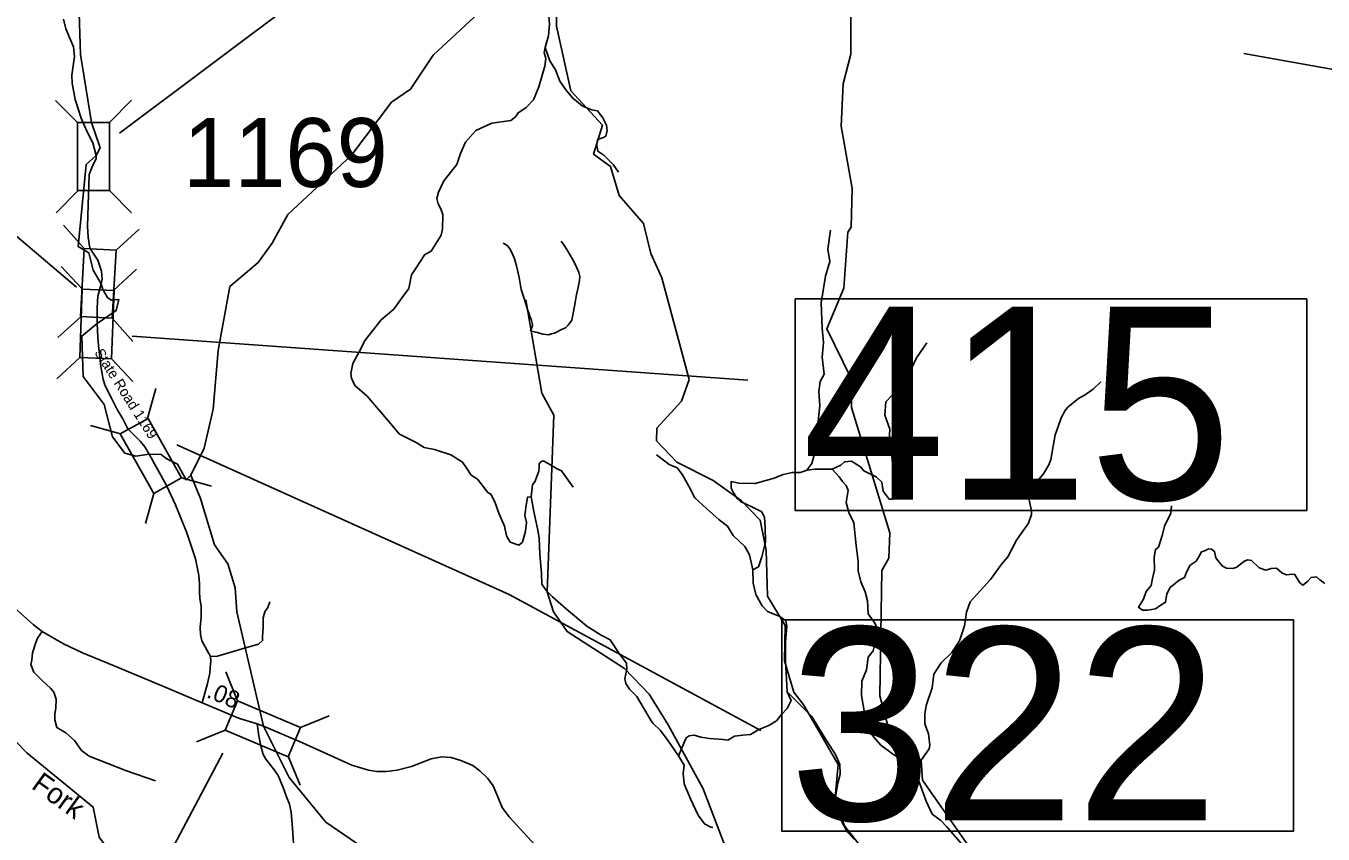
# Model space of a CAD drawing. Extents: x 1248224 to 1454986, y 825081 to 985870.
# Drawn here: x 1290579 to 1300002, y 874876 to 880743 of the extents above; entities that cross this region are included whole.
import ezdxf

# ---------------------------------------------------------------- set-up
doc = ezdxf.new("R2010")
doc.units = 0
for name, color, linetype in [('Exist Hydrographic Creek Single Shore', 7, 'Continuous'), ('Exist Hydrographic Creek Single Shore Label', 7, 'Continuous'), ('Exist Hydrographic Misc Water Feature', 7, 'Continuous'), ('Exist Road Non-System Type 51', 7, 'Continuous'), ('Exist Road Secondary Mileage Hundredths English Label', 7, 'Continuous'), ('Exist Road Secondary Structure Standard Bridge CELL', 7, 'Continuous'), ('Exist Road Secondary Structure Standard Bridge Number Label', 7, 'Continuous'), ('Exist Road Secondary Type 41 Attributed', 7, 'Continuous'), ('Exist Road Secondary Type 51 Attributed', 7, 'Continuous'), ('Exist Road Secondary Type 51 Label', 7, 'Continuous'), ('Exist Road Secondary Type 51 Number Label', 7, 'Continuous')]:
    doc.layers.add(name, color=color, linetype=linetype)

msp = doc.modelspace()

# ---------------------------------------------------------------- linework, layer by layer
at = {"layer": 'Exist Hydrographic Creek Single Shore'}
for points in [[(1291089.2, 879801.8), (1291118.8, 879857.6), (1291055.8, 880042.6), (1290976.7, 880536.6), (1290966.8, 880835.6)], [(1300225, 880400.4), (1299426.9, 880544.5)], [(1291126.6, 878871.1), (1291067.1, 878969.7), (1291036.4, 879096.4), (1290958.8, 879141.8), (1291016.8, 879737.6), (1291089.2, 879801.8)], [(1291097.8, 878582.1), (1291235.2, 878676.7), (1291253, 878756.9), (1291198.6, 878752.9), (1291172.9, 878771.7), (1291136.8, 878830.4), (1291126.6, 878871.1)], [(1291474.7, 877633.8), (1291378.7, 877620.9), (1291297.9, 877641.4), (1291208.9, 877761.3), (1291147.9, 877995.7), (1290993.9, 878199), (1290984.8, 878491.3), (1291097.8, 878582.1)], [(1291776.9, 877480.8), (1291742.8, 877447.7), (1291681.4, 877560.6), (1291596.8, 877602.5), (1291561.7, 877631.8), (1291474.7, 877633.8)], [(1292305.9, 875658.3), (1292111.9, 876489.2), (1292098.9, 876663.5), (1292044.9, 876838.5), (1291947.9, 876975.1), (1291847.9, 877311.9), (1291776.9, 877480.8)], [(1292627.6, 873988.5), (1292479.6, 873915.9), (1292338.8, 873797.9), (1292148.7, 873938.9), (1291945.6, 874109.4), (1291863.9, 874235.6), (1291719.1, 874279.3), (1291608.9, 874358.9), (1291493.9, 874426.9), (1291323.9, 874630.5), (1291192.9, 874741.4), (1291111.9, 874854.7), (1291067.9, 875072.3), (1290584.9, 875466.1), (1290015.9, 876048.6), (1289907.9, 876073.7)], [(1293365, 874546.9), (1292757.9, 874962.9), (1292491, 875286.7), (1292305.9, 875658.3)]]:
    msp.add_lwpolyline(points, dxfattribs=at)
at = {"layer": 'Exist Hydrographic Misc Water Feature'}
for points in [[(1298185, 873895.5), (1298130.1, 874031.1), (1297898.1, 874101.5), (1297446, 874681.8), (1297415.1, 874807), (1297093, 875266.6), (1297082.8, 875412), (1296844, 875655.6), (1296783, 875880.1), (1296796.9, 876789.2), (1296849, 876880), (1296854, 877063.8), (1296576, 877972.1), (1296572.9, 878188.9), (1296397.9, 878543.6), (1296522, 878839.9), (1296548.9, 879246.4), (1296575, 879282), (1296581.9, 879564.1), (1296501, 880015.6), (1296516.9, 880323.9), (1296571.9, 880539.4), (1296575.9, 881724.4)], [(1296712.1, 874699.7), (1296526, 874936.5), (1296456, 875115.2), (1296479, 875380.7), (1296231, 875812.4), (1296158, 875905.8), (1296089, 876133.6), (1296095, 876389.6), (1295967, 876602.3), (1295958, 876937.3), (1295914, 877154.9), (1295775, 877298.8), (1295570.9, 877444.1), (1295306.9, 877577.4), (1295160.9, 877731.3), (1295162.9, 877823.2), (1295342.9, 878019.8), (1295397, 878176.4), (1295198, 878915.7), (1295118.9, 879091.2), (1295065.9, 879309), (1294887.9, 879512.8), (1294825.9, 879724.1), (1294702.9, 879812), (1294766.8, 880024.1), (1294538.9, 880271.6), (1294433.8, 880743.1), (1294435.9, 881160)], [(1291776.9, 877480.8), (1291873.9, 877679), (1291938.9, 877960.1), (1291974.8, 878386.1), (1292060.9, 878850.6), (1292265.8, 879027), (1292368.8, 879166), (1292482.9, 879373.9), (1292943.8, 879804.6), (1293235.8, 880189.3), (1293371.9, 880285.1), (1293536.8, 880531.3), (1293869.8, 880839.8)], [(1294774, 873878.5), (1294918.1, 873957.7), (1295020, 874057.5), (1295178, 874346.4), (1295603, 874685.9), (1295663, 874773.3), (1295499, 875203.3), (1295244, 875668.1), (1295107, 875890.7), (1294928, 876078.2), (1294510, 876346), (1294412.9, 876489.1), (1294367, 876634.4), (1294415, 877917), (1294326.9, 878076.3), (1294209.9, 878754.9)], [(1298387.1, 878159.8), (1298331.8, 878105.1), (1298274.8, 878064.4), (1298226.1, 878037.5), (1298148.4, 877975.9), (1298127.8, 877951.6), (1298102.6, 877902.9), (1298057.5, 877775.8), (1298025.1, 877595.8), (1298010, 877556.8), (1297972.5, 877491.1), (1297927.2, 877440.3), (1297877.1, 877357.6), (1297867.7, 877301.9), (1297883.8, 877221.2), (1297883.2, 877197.4), (1297861.6, 877132.2), (1297776.6, 877010), (1297713.5, 876889.8), (1297668.2, 876838.2), (1297587.4, 876724.1), (1297439.3, 876562.1), (1297411.4, 876486.3), (1297397, 876388.9), (1297362.3, 876278), (1297306.2, 876194.6), (1297228.2, 876119.1), (1297174.2, 876036.4), (1297161.7, 875936.6), (1297118.6, 875809.3), (1297109, 875747.2), (1297109.2, 875675.7), (1297135.5, 875603.1), (1297145.5, 875522.4), (1297140.9, 875494.6), (1297082.8, 875412)]]:
    msp.add_lwpolyline(points, dxfattribs=at)
at = {"layer": 'Exist Road Non-System Type 51'}
for points in [[(1294349.1, 880939.6), (1294376, 880846.2), (1294381.9, 880754.6), (1294376, 880671.9), (1294352.4, 880586.2)], [(1294352.4, 880586.2), (1294343.5, 880550.8), (1294355.3, 880506.4), (1294349.4, 880450.3), (1294305.1, 880302.6), (1294266.8, 880208), (1294210.7, 880148.9), (1294154.6, 880113.5), (1294136.8, 880083.9), (1294101.4, 880057.3), (1293962.7, 880036.7), (1293847.5, 879983.5), (1293773.7, 879900.8), (1293735.3, 879818), (1293709.1, 879737.8), (1293614.7, 879619.7), (1293576.3, 879536.9), (1293564.5, 879489.7), (1293573.3, 879451.2), (1293594, 879415.8), (1293608.7, 879374.4), (1293605.8, 879268.1), (1293596.9, 879223.7), (1293523.1, 879108.5), (1293475.9, 879084.9), (1293413.9, 878987.4), (1293381.4, 878937.2), (1293360.7, 878836.7), (1293313.5, 878771.7), (1293251.5, 878686), (1293160, 878609.2), (1293044.8, 878461.5), (1293003.5, 878381.7), (1292953.8, 878291.6), (1292939, 878220.7), (1292944.9, 878185.2), (1292968.6, 878132), (1293057.1, 878055.2), (1293157.5, 877940), (1293228.4, 877857.2), (1293293.3, 877780.4), (1293414.4, 877718.4), (1293473.4, 877682.9), (1293547.2, 877668.2), (1293665.3, 877629.7), (1293751, 877576.6), (1293777.5, 877538.2), (1293813, 877482), (1293860.2, 877452.5), (1293935.6, 877356.7), (1293956.3, 877344.9), (1293985.8, 877288.7), (1294015.3, 877206), (1294056.6, 877111.4), (1294071.4, 877040.5), (1294098, 876996.2), (1294160, 876972.6), (1294186.5, 876996.2), (1294207.2, 877076), (1294216.1, 877138), (1294204.3, 877188.3), (1294210.2, 877247.4), (1294222, 877321.2), (1294248.5, 877324.2)], [(1294352.4, 880586.2), (1294385.1, 880490.7), (1294426.3, 880424.4), (1294458.3, 880342), (1294501.8, 880280.2), (1294552.1, 880218.4), (1294620.7, 880163.5), (1294687, 880133.7), (1294730.5, 880126.8), (1294769.3, 880076.5), (1294796.8, 880023.9), (1294801.3, 879985), (1294792.2, 879943.8), (1294773.9, 879934.6), (1294730.5, 879918.6), (1294725.9, 879879.7), (1294735, 879833.9), (1294778.5, 879806.4), (1294844.8, 879737.8), (1294883.7, 879682.9)], [(1296251.1, 877517.4), (1296288.1, 877567), (1296315.5, 877663.1), (1296322.4, 877731.8), (1296336.1, 877896.6), (1296346.4, 877985.8), (1296339.5, 878088.8), (1296349.8, 878160.9), (1296377.3, 878215.8), (1296363.5, 878339.4), (1296373.8, 878445.8), (1296363.5, 878548.8), (1296356.7, 878734.2), (1296387.5, 878926.4), (1296418.2, 879033.5), (1296404.5, 879122.8), (1296425.1, 879260.1)], [(1294245.4, 878526.4), (1294260.2, 878568.1), (1294260.4, 878576.1), (1294250.9, 878604.3), (1294237.7, 878644.6), (1294222.5, 878684.9), (1294203.8, 878749.3), (1294177.4, 878829.9), (1294163.1, 878918.2), (1294142.8, 879002.7), (1294127.8, 879053), (1294110.6, 879093.4), (1294095.3, 879125.7), (1294081.6, 879142), (1294067.8, 879154.3), (1294046, 879166.7)], [(1294245.4, 878526.4), (1294263.3, 878524), (1294283.2, 878519.6), (1294295.2, 878517.4), (1294335, 878506.5), (1294356.9, 878502.1), (1294378.9, 878501.7), (1294395.1, 878507.3), (1294419.2, 878512.9), (1294475.8, 878541.7), (1294500, 878551.3), (1294518.4, 878570.9), (1294545.2, 878608.4), (1294556.4, 878670.2), (1294569.7, 878736), (1294578.9, 878793.8), (1294589.9, 878843.6), (1294596.5, 878871.5), (1294601, 878895.5), (1294603.6, 878925.4), (1294596.1, 878953.6), (1294575.1, 879004), (1294550, 879050.6), (1294517.1, 879107.3), (1294495.8, 879139.7), (1294466.6, 879180.3)], [(1295860, 876794.5), (1295901.2, 876817.1), (1295925.2, 876889.2), (1295952.7, 876995.6), (1295949.3, 877098.6), (1295945.8, 877174.1), (1295925.2, 877215.3), (1295856.6, 877249.6), (1295770.9, 877290.8), (1295746.9, 877311.4), (1295719.4, 877352.6), (1295702.3, 877387), (1295702.3, 877435), (1295757.2, 877424.7), (1295877.2, 877421.3), (1296014.4, 877459), (1296079.6, 877486.5), (1296144.8, 877500.2), (1296206.5, 877500.2), (1296251.1, 877517.4), (1296309.4, 877524.3), (1296384.9, 877524.3), (1296436.4, 877524.3), (1296498.1, 877555.2), (1296525.6, 877579.2), (1296577, 877582.6), (1296642.2, 877541.4), (1296666.2, 877514), (1296755.4, 877469.3), (1296796.6, 877431.6), (1296806.9, 877366.4), (1296851.4, 877308), (1296874.6, 877306.6), (1296881.5, 877323.8), (1296898.6, 877354.7), (1296888.4, 877389), (1296874.6, 877461.1), (1296874.6, 877567.5), (1296867.8, 877643), (1296847.2, 877694.5), (1296854.1, 877814.7), (1296819.8, 877917.7), (1296826.6, 878013.8), (1296871.2, 878061.9), (1296943.2, 878103.1), (1296991.3, 878209.5), (1297049.6, 878333.1), (1297125.1, 878442.9)], [(1295860, 876794.5), (1295836.1, 876902.9), (1295801.8, 876964.7), (1295716, 877043.7), (1295674.8, 877112.3), (1295616.5, 877157), (1295523.9, 877239.3), (1295438.1, 877318.3), (1295397, 877397.3), (1295348.9, 877483.1), (1295311.2, 877534.6), (1295252.9, 877558.6), (1295198, 877599.8), (1295160.3, 877630.7)], [(1294248.5, 877324.2), (1294257.4, 877389.2), (1294260.4, 877412.8), (1294278.1, 877439.4), (1294289.9, 877471.9), (1294304.6, 877510.3), (1294307.6, 877539.9), (1294307.6, 877563.5), (1294319.4, 877578.3), (1294337.1, 877587.1), (1294372.5, 877566.4), (1294434.5, 877531), (1294470, 877513.3), (1294555.6, 877395.1)], [(1296436.4, 877524.3), (1296487.6, 877469.5), (1296511.6, 877435.2), (1296539, 877407.7), (1296552.8, 877369.9), (1296539, 877284.1), (1296556.2, 877212), (1296593.9, 877136.5), (1296611.1, 876971.7), (1296624.8, 876855), (1296624.8, 876786.3), (1296645.4, 876707.4), (1296676.3, 876635.3), (1296693.4, 876570.1), (1296696.8, 876474), (1296741.4, 876415.6), (1296762, 876374.4), (1296751.7, 876274.9), (1296734.6, 876206.2), (1296696.8, 876161.6), (1296686.6, 876068.9), (1296652.1, 875986.1), (1296648.7, 875883.1), (1296672.7, 875742.3), (1296689.8, 875642.8), (1296741.3, 875577.5), (1296789.3, 875522.6), (1296875.1, 875457.4), (1296943.7, 875416.2), (1297012.3, 875371.6), (1297043.2, 875320.1), (1297118.6, 875114.1), (1297163.2, 875021.4), (1297225, 874973.4), (1297269.6, 874928.7), (1297379.3, 874801.7)], [(1294248.5, 877324.2), (1294269.2, 877218.8), (1294298.7, 877082.9), (1294307.6, 877026.8), (1294313.5, 876905.6), (1294325.3, 876769.7), (1294328.2, 876690), (1294357.7, 876645.6), (1294405, 876598.4), (1294505.4, 876509.7), (1294653, 876385.6), (1294759.3, 876320.6), (1294824.2, 876285.2), (1294889.2, 876187.7), (1294942.3, 876116.8), (1294945.3, 876072.5), (1294930.5, 876004.5), (1294936.4, 875969.1), (1294963, 875927.7), (1295016.1, 875874.5), (1295121.5, 875699), (1295136.3, 875678.3), (1295186.4, 875631.1), (1295239.6, 875560.2), (1295319.3, 875444.9)], [(1300015.1, 876695.4), (1299978.7, 876722.1), (1299954.4, 876744), (1299915.5, 876739.1), (1299888.9, 876710), (1299854.9, 876683.3), (1299833, 876700.3), (1299794.2, 876763.4), (1299755.4, 876761), (1299733.5, 876758.6), (1299702, 876773.1), (1299663.1, 876807.1), (1299626.7, 876804.7), (1299587.9, 876792.6), (1299539.4, 876809.6), (1299483.5, 876863), (1299454.4, 876867.8), (1299427.7, 876855.7), (1299376.8, 876814.4), (1299347.6, 876804.7), (1299301.5, 876807.1), (1299272.4, 876821.7), (1299248.1, 876850.8), (1299223.8, 876882.4), (1299213.1, 876928), (1299191.3, 876945), (1299169.5, 876947.4), (1299147.6, 876935.2), (1299118.5, 876925.5), (1299099.1, 876889.1), (1299079.7, 876857.5), (1299036, 876828.4), (1299009.3, 876777.4), (1298997.1, 876738.5), (1298958.3, 876719.1), (1298931.6, 876697.2), (1298892.8, 876665.7), (1298868.5, 876619.5), (1298858.8, 876558.8), (1298827.3, 876539.4), (1298786, 876510.2), (1298727.7, 876502.9), (1298691.3, 876500.5), (1298662.2, 876522.4), (1298698.6, 876580.6), (1298718, 876636.5), (1298754.4, 876680.2), (1298764.1, 876731.2), (1298778.7, 876794.4), (1298776.3, 876886.7), (1298786, 876942.5), (1298807.8, 876959.5), (1298837, 877051.8), (1298851.5, 877112.6), (1298897.6, 877204.8), (1298902.5, 877258.3)], [(1295319.3, 875444.9), (1295376.4, 875575.8), (1295396.9, 875589.5), (1295434.7, 875593), (1295482.7, 875579.2), (1295544.4, 875569), (1295643.9, 875562.1), (1295678.2, 875558.7), (1295726.3, 875586.1), (1295788, 875593), (1295842.9, 875599.8), (1295904.6, 875634.2), (1295976.7, 875665.1), (1296031.6, 875699.4), (1296069.3, 875744), (1296110.5, 875788.7), (1296137.9, 875847), (1296110.5, 875908.8), (1296096.7, 876135.4), (1296096.7, 876265.8), (1296107, 876386), (1296100.2, 876423.7), (1296055.6, 876454.6), (1295966.4, 876492.4), (1295928.6, 876533.6), (1295880.6, 876616), (1295863.5, 876698.4), (1295860, 876794.5)], [(1291919.8, 876166.5), (1291970.2, 876168.4), (1292150.3, 876221.6), (1292241.8, 876248.1), (1292268.4, 876254.1), (1292297.9, 876280.6), (1292297.9, 876310.2), (1292303.8, 876375.2), (1292303.8, 876446.1), (1292315.6, 876490.4), (1292336.3, 876520), (1292351.1, 876561.3)], [(1290697.3, 876347.1), (1290663.1, 876299.1), (1290651.3, 876266.6), (1290627.7, 876192.7), (1290621.8, 876139.5), (1290615.9, 876107), (1290636.5, 876050.9), (1290698.5, 875988.9), (1290757.6, 875935.7), (1290781.2, 875906.1), (1290798.9, 875855.9), (1290796, 875790.9), (1290790, 875749.5), (1290790, 875705.2), (1290804.8, 875649.1), (1290869.8, 875610.7), (1290931.8, 875554.5), (1290982, 875483.6), (1291038.1, 875442.3), (1291309.7, 875335.9), (1291519.3, 875262)], [(1296596.5, 874838), (1296545, 874892.9), (1296501, 874973.6), (1296466.7, 875062.9), (1296459.9, 875145.2), (1296477, 875244.8), (1296494.2, 875310), (1296490.8, 875382.1), (1296459.9, 875454.2), (1296377.6, 875581.2), (1296288.4, 875728.8), (1296110.5, 875908.8), (1296137.9, 875847)], [(1295319.3, 875444.9), (1295360.6, 875377), (1295354.7, 875314.9), (1295360.6, 875241.1), (1295407.9, 875131.8), (1295464, 875013.6), (1295508.1, 874950.1), (1295555.3, 874926.5), (1295570.1, 874923.5)]]:
    msp.add_lwpolyline(points, dxfattribs=at)
at = {"layer": 'Exist Road Secondary Structure Standard Bridge CELL'}
for p, q in [((1290794.7, 880203.3), (1290954.8, 880043.3)), ((1291346.4, 880203.5), (1291186.4, 880043.4)), ((1290959.1, 879547.6), (1290799.1, 879387.5)), ((1291185.4, 879547.6), (1291345.6, 879387.6)), ((1290851.9, 879297.2), (1291002.9, 879128.6)), ((1291402.7, 879266.8), (1291234.1, 879115.8)), ((1290989.9, 878831.5), (1290836, 878997.5)), ((1291216.1, 878822.9), (1291382.1, 878976.7)), ((1290979.7, 878633.3), (1290811.1, 878482.3)), ((1291205.8, 878620.9), (1291356.8, 878452.2)), ((1290803.9, 878182.3), (1290969.9, 878336.1)), ((1291355.2, 878161.3), (1291201.3, 878327.3)), ((1291462.7, 877892.5), (1291523.5, 878110.5)), ((1291265.5, 877781.3), (1291047.5, 877842.1)), ((1291927.8, 877401.9), (1291709.8, 877462.7)), ((1291447.3, 877130.9), (1291508.1, 877349)), ((1292032, 876053.2), (1292117.1, 875843.5)), ((1292573.4, 875649.6), (1292783.1, 875734.8)), ((1291817.3, 875545), (1292027, 875630.1)), ((1292485.4, 875441.1), (1292570.5, 875231.4))]:
    msp.add_line(p, q, dxfattribs=at)
for points in [[(1291186.4, 880043.4), (1291186.5, 879547.6), (1290954.9, 879547.6), (1290954.8, 880043.3)], [(1291234.1, 879115.8), (1291206.8, 878620.8), (1290975.6, 878633.5), (1291002.9, 879128.6)], [(1290969.9, 878336.1), (1290988.8, 878831.5), (1291220.2, 878822.7), (1291201.3, 878327.3)], [(1291508.1, 877349), (1291264.6, 877780.8), (1291466.3, 877894.5), (1291709.8, 877462.7)], [(1292117.1, 875843.5), (1292573.8, 875650.6), (1292483.7, 875437.3), (1292027, 875630.1)]]:
    msp.add_lwpolyline(points, close=True, dxfattribs=at)
at = {"layer": 'Exist Road Secondary Structure Standard Bridge Number Label'}
for p, q in [((1290947.6, 878846.4), (1286961.2, 882216.8)), ((1291258.3, 879964.7), (1292953.7, 881236.2)), ((1291352, 878490.4), (1295824.7, 878170.9)), ((1292008.9, 875464.1), (1289936.5, 871537.4))]:
    msp.add_line(p, q, dxfattribs=at)
for points in [[(1296167.6, 878761.7), (1299883.5, 878761.7), (1299883.5, 877225.2), (1296167.6, 877225.2)], [(1296070.8, 876432.7), (1299786.7, 876432.7), (1299786.7, 874896.3), (1296070.8, 874896.3)]]:
    msp.add_lwpolyline(points, close=True, dxfattribs=at)
msp.add_lwpolyline([(1291676.2, 877703), (1294089.5, 876615.2), (1295917.7, 875628)], dxfattribs=at)
at = {"layer": 'Exist Road Secondary Type 41 Attributed'}
msp.add_lwpolyline([(1292258.4, 875675.9), (1292271.8, 875589.8), (1292286.6, 875517.7), (1292302.9, 875453.7), (1292322.6, 875419.3), (1292376.7, 875350.5), (1292412.7, 875301.3), (1292448.7, 875214.4), (1292473.1, 875146.3), (1292494.4, 875093.8), (1292505.9, 875031.5), (1292515.7, 874920), (1292528.8, 874735.4), (1292533.7, 874632.1), (1292541.9, 874550.1), (1292579, 874261.4), (1292592.7, 874149.6), (1292595.9, 874093.7), (1292595.9, 874034.7), (1292607.1, 874003.7), (1292627.6, 873988.5)], dxfattribs=at)
at = {"layer": 'Exist Road Secondary Type 51 Attributed'}
for points in [[(1291089.2, 879801.8), (1291064.9, 879894.7), (1291020.8, 879979.5), (1290980.1, 880072.8), (1290937.7, 880208.5), (1290915.7, 880328.9), (1290912.3, 880386.6), (1290932.6, 880520.6), (1290924.1, 880592.8), (1290895.3, 880659), (1290869.9, 880723.5), (1290852.9, 880793)], [(1291126.6, 878871.1), (1291132.4, 878904.4), (1291127.4, 878962.8), (1291101.7, 879043.9), (1291044.3, 879130.2), (1291031.2, 879208.9), (1291026.2, 879289.3), (1291032.8, 879519), (1291037.7, 879664.9), (1291062.3, 879727.2), (1291088.5, 879778), (1291089.2, 879801.8)], [(1291097.8, 878582.1), (1291096.1, 878696.6), (1291102, 878781.4), (1291126.6, 878871.1)], [(1291474.7, 877633.8), (1291441.8, 877686.7), (1291410.7, 877726), (1291369.7, 877767), (1291320.6, 877819.5), (1291282.9, 877891.6), (1291242.5, 877957.8), (1291201.5, 878039.8), (1291155.7, 878130), (1291140.9, 878177.5), (1291124.5, 878271), (1291105.4, 878424.3), (1291101.1, 878482.9), (1291097.8, 878582.1)], [(1291859.2, 875828.6), (1291574.7, 875951), (1291381.4, 876029.7), (1291219.2, 876097), (1290988.9, 876191.4), (1290851.3, 876256.9), (1290754.6, 876312.7), (1290697.3, 876347.1), (1290635, 876396.3), (1290561.3, 876460.2), (1290371.8, 876625.3), (1290085.1, 876874.5), (1289903.3, 877035.1), (1289843.4, 877086.4), (1289784.4, 877134), (1289645.2, 877214.3), (1289497.7, 877296.3), (1289424, 877338.9), (1289342.1, 877404.5), (1289217.6, 877507.8), (1289101.3, 877617.6), (1288982, 877742.4)], [(1291859.2, 875828.6), (1291898.5, 875969.8), (1291914.9, 876043.5), (1291918.2, 876086.2), (1291921.4, 876132.1), (1291919.8, 876166.5), (1291882.1, 876235.4), (1291857.5, 876278), (1291847.7, 876323.9), (1291846.1, 876376.4), (1291851, 876451.8), (1291851.1, 876530.9), (1291842.9, 876586.6), (1291841.2, 876637.5), (1291839.6, 876693.2), (1291836.3, 876752.2), (1291811.7, 876875.2), (1291747.8, 877062.1), (1291666, 877265.9), (1291600.5, 877406.9), (1291474.7, 877633.8)], [(1292258.4, 875675.9), (1292131.5, 875715.8), (1291859.2, 875828.6)], [(1292305.9, 875658.3), (1292258.4, 875675.9)], [(1294304.7, 874766), (1294088.6, 875001.4), (1294037.7, 875069.8), (1294007.9, 875146.8), (1293973, 875226.4), (1293934.8, 875278.9), (1293876, 875336.1), (1293825.2, 875372.7), (1293737.7, 875410.9), (1293669.4, 875431.6), (1293601, 875436.3), (1293523.2, 875422), (1293379.5, 875366.2), (1293276.2, 875340.8), (1293198.3, 875331.2), (1293128.4, 875331.2), (1293068, 875339.2), (1292945.6, 875377.3), (1292589, 875539.5), (1292305.9, 875658.3)]]:
    msp.add_lwpolyline(points, dxfattribs=at)

# ---------------------------------------------------------------- texts
at = {"layer": 'Exist Hydrographic Creek Single Shore Label'}
msp.add_text('Fork', height=150, rotation=324.20193, dxfattribs=at).set_placement((1290610.8, 875212.8))
at = {"layer": 'Exist Road Secondary Mileage Hundredths English Label'}
msp.add_text('.08', height=125, rotation=337.50452, dxfattribs=at).set_placement((1291884.3, 875871.4))
at = {"layer": 'Exist Road Secondary Structure Standard Bridge Number Label'}
for s, p in [('415', (1296217.8, 877304.3)), ('322', (1296121, 874975.4))]:
    msp.add_text(s, height=1400, dxfattribs=at).set_placement(p)
at = {"layer": 'Exist Road Secondary Type 51 Label'}
msp.add_text('State Road 1169', height=75, rotation=302.46911, dxfattribs=at).set_placement((1291073.5, 878371.7))
at = {"layer": 'Exist Road Secondary Type 51 Number Label'}
msp.add_text('1169', height=500, dxfattribs=at).set_placement((1291720.4, 879574.5))

doc.saveas('drawing.dxf')
